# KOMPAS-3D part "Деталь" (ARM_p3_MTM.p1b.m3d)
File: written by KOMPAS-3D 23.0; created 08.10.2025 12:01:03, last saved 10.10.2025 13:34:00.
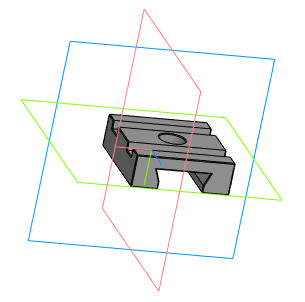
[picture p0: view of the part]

Document properties: Автор: ADMIN; Полное имя файла: D:\YandexDisk\Model\NVG\ARM mkII\ARM p3 MTM.p1b.m3d

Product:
- Part/product: Деталь
    Масса: 0.02252

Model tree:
1. Эскиз:1
2. Элемент выдавливания:1
     Расстояние 1 = 25
3. Эскиз:2  (with: Элемент выдавливания:1)
4. Элемент выдавливания:2
5. Эскиз:3  (with: Элемент выдавливания:1)
6. Элемент выдавливания:3
     Расстояние 2 = 24
7. Фаска:1  (with: Элемент выдавливания:1, Элемент выдавливания:2)
     Угол = 45; Длина 1 = 0.2; Длина 2 = 0.2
